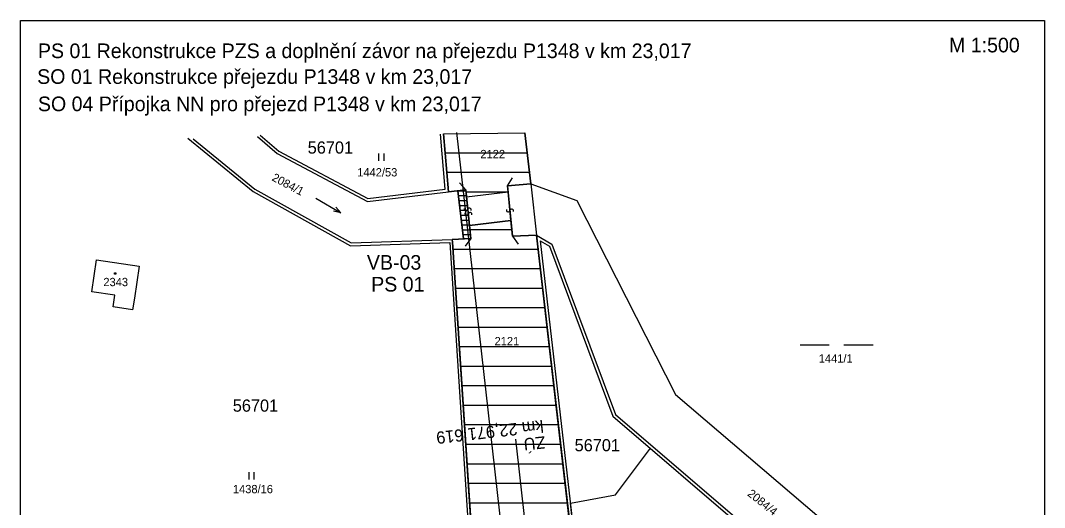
# Model space of a CAD drawing. Extents: x -792659 to -786947, y -1118170 to -1109641.
# Drawn here: x -792658.7 to -792553.7, y -1110443.9 to -1110394 of the extents above; entities that cross this region are included whole.
import ezdxf

# ---------------------------------------------------------------- set-up
doc = ezdxf.new("R2010")
doc.units = 0
doc.layers.add('1', color=7, linetype='Continuous')

# ---------------------------------------------------------------- blocks, each defined once
blk = doc.blocks.new('Z4022')
at = {"layer": '1'}
for p, q in [((-0.1, 0.1), (0.2, 0.1)), ((-0.1, -0.2), (-0.1, 0.1)), ((0.2, 0.1), (0.2, -0.2)), ((0.2, -0.2), (-0.1, -0.2))]:
    blk.add_line(p, q, dxfattribs=at)
blk = doc.blocks.new('Z42000')
at = {"layer": '1'}
blk.add_line((0, 0), (-0.7, -0.7), dxfattribs=at)
blk = doc.blocks.new('Z30602')
at = {"layer": '1'}
for p, q in [((-0.5, 0), (-0.5, 1.5)), ((0.5, 1.5), (0.5, 0))]:
    blk.add_line(p, q, dxfattribs=at)
blk = doc.blocks.new('Z8032')
at = {"layer": '1'}
for p, q in [((-7.5, 0), (-1.5, 0)), ((1.5, 0), (7.5, 0))]:
    blk.add_line(p, q, dxfattribs=at)
blk = doc.blocks.new('Z8021')
at = {"layer": '1'}
for p, q in [((-3, 0), (3, 0)), ((3, 0), (1.5, 0.5)), ((3, 0), (1.5, -0.5))]:
    blk.add_line(p, q, dxfattribs=at)

msp = doc.modelspace()

# ---------------------------------------------------------------- linework, layer by layer
at = {"layer": '1'}
for p, q in [((-792641.51, -1110406.04), (-792634.82, -1110411.52)), ((-792640.98, -1110406.09), (-792634.65, -1110411.27)), ((-792634.39, -1110405.88), (-792632.37, -1110407.62)), ((-792634.1, -1110405.74), (-792632.2, -1110407.37)), ((-792615.13, -1110411.27), (-792615.61, -1110405.63)), ((-792615.31, -1110405.6), (-792614.81, -1110411.53)), ((-792613.96, -1110405.45), (-792608.61, -1110452.76)), ((-792606.36, -1110410.71), (-792606.96, -1110405.48)), ((-792632.2, -1110407.37), (-792623.05, -1110412.21)), ((-792615.15, -1110407.53), (-792606.73, -1110407.53)), ((-792632.37, -1110407.62), (-792623.11, -1110412.52)), ((-792614.98, -1110409.53), (-792606.5, -1110409.53)), ((-792613.01, -1110411.35), (-792613.66, -1110410.6)), ((-792608.74, -1110410.94), (-792608.23, -1110410.09)), ((-792634.82, -1110411.52), (-792624.85, -1110417.07)), ((-792634.65, -1110411.27), (-792624.78, -1110416.77)), ((-792623.11, -1110412.52), (-792614.81, -1110411.53)), ((-792623.05, -1110412.21), (-792615.13, -1110411.27)), ((-792614.81, -1110411.53), (-792613.01, -1110411.35)), ((-792614.81, -1110411.53), (-792613.01, -1110411.35)), ((-792613.83, -1110411.43), (-792613.27, -1110416.35)), ((-792613.83, -1110411.43), (-792613, -1110411.43)), ((-792613.01, -1110411.35), (-792612.94, -1110412.04)), ((-792613.01, -1110411.35), (-792612.51, -1110416.31)), ((-792613.01, -1110411.35), (-792612.94, -1110412.04)), ((-792612.99, -1110411.53), (-792608.68, -1110411.53)), ((-792612.94, -1110412.04), (-792608.68, -1110411.53)), ((-792612.94, -1110412.04), (-792608.68, -1110411.53)), ((-792608.74, -1110410.94), (-792606.36, -1110410.71)), ((-792606.36, -1110410.71), (-792608.74, -1110410.94)), ((-792608.68, -1110411.53), (-792608.74, -1110410.94)), ((-792608.74, -1110410.94), (-792608.23, -1110416.1)), ((-792608.39, -1110414.49), (-792608.68, -1110411.53)), ((-792606.36, -1110410.71), (-792601.62, -1110412.42)), ((-792606.36, -1110410.71), (-792605.76, -1110415.98)), ((-792613.77, -1110411.93), (-792612.95, -1110411.93)), ((-792613.72, -1110412.43), (-792612.9, -1110412.43)), ((-792612.65, -1110414.98), (-792612.94, -1110412.04)), ((-792601.62, -1110412.42), (-792591.51, -1110432.33)), ((-792613.66, -1110412.93), (-792612.85, -1110412.93)), ((-792613.6, -1110413.43), (-792612.8, -1110413.43)), ((-792613.55, -1110413.93), (-792612.75, -1110413.93)), ((-792613.49, -1110414.43), (-792612.7, -1110414.43)), ((-792608.39, -1110414.49), (-792612.65, -1110414.98)), ((-792612.65, -1110414.98), (-792608.39, -1110414.49)), ((-792608.23, -1110416.1), (-792608.39, -1110414.49)), ((-792613.43, -1110414.93), (-792612.66, -1110414.93)), ((-792613.38, -1110415.43), (-792612.6, -1110415.43)), ((-792613.32, -1110415.93), (-792612.55, -1110415.93)), ((-792612.65, -1110414.98), (-792612.51, -1110416.31)), ((-792612.51, -1110416.31), (-792612.65, -1110414.98)), ((-792612.6, -1110415.41), (-792608.3, -1110415.41)), ((-792624.85, -1110417.07), (-792614.67, -1110416.72)), ((-792624.78, -1110416.77), (-792614.4, -1110416.41)), ((-792614.67, -1110416.72), (-792612.15, -1110455.3)), ((-792612.51, -1110416.31), (-792614.4, -1110416.41)), ((-792612.51, -1110416.31), (-792614.4, -1110416.41)), ((-792614.4, -1110416.41), (-792614.37, -1110416.71)), ((-792614.37, -1110416.71), (-792611.85, -1110455.28)), ((-792612.51, -1110416.31), (-792613.08, -1110417.12)), ((-792605.76, -1110415.98), (-792608.23, -1110416.1)), ((-792608.23, -1110416.1), (-792605.76, -1110415.98)), ((-792608.23, -1110416.1), (-792607.66, -1110416.91)), ((-792605.76, -1110415.98), (-792604.19, -1110416.91)), ((-792605.76, -1110415.98), (-792598.74, -1110476.89)), ((-792598.74, -1110476.89), (-792605.76, -1110415.98)), ((-792598.74, -1110476.89), (-792605.76, -1110415.98)), ((-792605.39, -1110416.55), (-792604.43, -1110417.11)), ((-792605.39, -1110416.55), (-792598.46, -1110476.7)), ((-792604.19, -1110416.91), (-792597.68, -1110434.36)), ((-792614.33, -1110417.41), (-792605.59, -1110417.41)), ((-792604.43, -1110417.11), (-792597.93, -1110434.54)), ((-792651.35, -1110421.79), (-792650.87, -1110418.51)), ((-792650.87, -1110418.51), (-792646.52, -1110419.16)), ((-792646.52, -1110419.16), (-792647, -1110422.44)), ((-792614.2, -1110419.41), (-792605.36, -1110419.41)), ((-792648.99, -1110422.14), (-792651.35, -1110421.79)), ((-792649.17, -1110423.34), (-792648.99, -1110422.14)), ((-792614.07, -1110421.41), (-792605.13, -1110421.41)), ((-792647, -1110422.44), (-792647.18, -1110423.63)), ((-792647.18, -1110423.63), (-792649.17, -1110423.34)), ((-792613.93, -1110423.41), (-792604.9, -1110423.41)), ((-792613.8, -1110425.41), (-792604.67, -1110425.41)), ((-792613.67, -1110427.41), (-792604.44, -1110427.41)), ((-792613.54, -1110429.41), (-792604.21, -1110429.41)), ((-792613.4, -1110431.41), (-792603.98, -1110431.41)), ((-792591.51, -1110432.33), (-792553.68, -1110464.6)), ((-792613.27, -1110433.41), (-792603.75, -1110433.41)), ((-792597.93, -1110434.54), (-792553.68, -1110472.43)), ((-792597.68, -1110434.36), (-792553.68, -1110472.03)), ((-792613.14, -1110435.41), (-792603.52, -1110435.41)), ((-792613, -1110437.41), (-792603.29, -1110437.41)), ((-792612.87, -1110439.41), (-792603.06, -1110439.41)), ((-792612.74, -1110441.41), (-792602.83, -1110441.41)), ((-792612.6, -1110443.41), (-792602.6, -1110443.41)), ((-792598.46, -1110476.7), (-792602.29, -1110443.46)), ((-792598.46, -1110476.7), (-792602.29, -1110443.46))]:
    msp.add_line(p, q, dxfattribs=at)
for points in [[(-792658.68, -1110393.97), (-792553.68, -1110393.97), (-792553.68, -1110542.47), (-792658.68, -1110542.47)], [(-792615.31, -1110405.6), (-792606.96, -1110405.48), (-792606.36, -1110410.71), (-792608.74, -1110410.94), (-792608.23, -1110416.1), (-792605.76, -1110415.98), (-792598.74, -1110476.89), (-792597.37, -1110489.98), (-792596.92, -1110494.31), (-792594.86, -1110514.07), (-792592.65, -1110517.65), (-792588.58, -1110542.47), (-792602.79, -1110542.47), (-792605.8, -1110489.46), (-792606.89, -1110485.01), (-792609.51, -1110474.26), (-792610.94, -1110468.39), (-792611.85, -1110455.28), (-792614.37, -1110416.71), (-792614.4, -1110416.41), (-792612.51, -1110416.31), (-792613.01, -1110411.35), (-792614.81, -1110411.53)], [(-792613.83, -1110411.43), (-792613.01, -1110411.35), (-792612.51, -1110416.31), (-792613.27, -1110416.35)]]:
    msp.add_lwpolyline(points, close=True, dxfattribs=at)
for points in [[(-792607.94, -1110436.89), (-792605.57, -1110457.95), (-792605.12, -1110461.93), (-792603.37, -1110477.43), (-792602.17, -1110488.16), (-792596.75, -1110536.28)], [(-792602.29, -1110443.46), (-792597.68, -1110442.6), (-792594.09, -1110437.83)]]:
    msp.add_lwpolyline(points, dxfattribs=at)
for centre, radius, start, end in [((-792613.01, -1110413.29), 0.188, 163.2102, 343.2102), ((-792612.94, -1110413.74), 0.188, 163.2102, 343.2102), ((-792612.65, -1110413.39), 0.187, 343.2102, 163.2102), ((-792612.58, -1110413.85), 0.187, 343.2102, 163.2102), ((-792608.67, -1110413.41), 0.188, 163.2102, 343.2102), ((-792608.31, -1110413.51), 0.187, 343.2102, 163.2102)]:
    msp.add_arc(centre, radius, start, end, dxfattribs=at)

# ---------------------------------------------------------------- block references
at = {"layer": '1', "xscale": 0.5, "yscale": 0.5}
for name, p in [('Z30602', (-792621.69, -1110408.37)), ('Z4022', (-792648.99, -1110419.88)), ('Z8032', (-792575, -1110427.21)), ('Z30602', (-792634.99, -1110441.02))]:
    msp.add_blockref(name, p, dxfattribs=at)
at = {"layer": '1'}
for p, rotation in [((-792613.01, -1110411.35), -94.2209), ((-792608.74, -1110410.94), -165.96380000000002), ((-792612.51, -1110416.31), 9.5989), ((-792608.23, -1110416.1), 80.1679)]:
    msp.add_blockref('Z42000', p, dxfattribs=dict(at, rotation=rotation))
at = {"layer": '1', "xscale": 0.5, "yscale": 0.5, "rotation": -30.490034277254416}
msp.add_blockref('Z8021', (-792627.12, -1110412.94), dxfattribs=at)

# ---------------------------------------------------------------- texts
at = {"layer": '1'}
for s, height, p in [('M 1:500', 1.5, (-792563.47, -1110397.24)), ('PS 01 Rekonstrukce PZS a doplnění závor na přejezdu P1348 v km 23,017', 1.5, (-792656.89, -1110397.83)), ('SO 01 Rekonstrukce přejezdu P1348 v km 23,017', 1.5, (-792656.97, -1110400.47)), ('SO 04 Přípojka NN pro přejezd P1348 v km 23,017', 1.5, (-792656.89, -1110403.27)), ('56701', 1.25, (-792629.23, -1110407.62)), ('2122', 0.85, (-792611.52, -1110408.09)), ('1442/53', 0.85, (-792624.15, -1110409.96)), ('VB-03', 1.5, (-792623.16, -1110419.52)), ('2343', 0.85, (-792650.18, -1110421.21)), ('PS 01', 1.5, (-792622.72, -1110421.76)), ('2121', 0.85, (-792610.07, -1110427.27)), ('1441/1', 0.85, (-792576.83, -1110429.05)), ('56701', 1.25, (-792636.91, -1110434.08)), ('56701', 1.25, (-792601.86, -1110438.14)), ('1438/16', 0.85, (-792636.9, -1110442.44))]:
    msp.add_text(s, height=height, dxfattribs=at).set_placement(p)
for s, height, rotation, p in [('2084/1', 0.85, 332.0441, (-792632.98, -1110410.33)), ('km 22,971 619', 1.25, 186.4259, (-792605.12, -1110434.92)), ('ZÚ', 1.25, 186.0649, (-792604.93, -1110436.59)), ('2084/4', 0.85, 321.3139, (-792584.21, -1110442.62))]:
    msp.add_text(s, height=height, rotation=rotation, dxfattribs=at).set_placement(p)

doc.saveas('drawing.dxf')
